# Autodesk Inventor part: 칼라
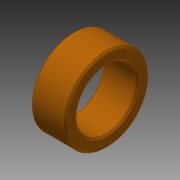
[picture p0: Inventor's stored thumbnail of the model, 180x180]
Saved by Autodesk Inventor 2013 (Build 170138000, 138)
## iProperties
Created: 2015-09
Part Number: 칼라
Material: 강철, 연강
Document SubType Name: Modeling
Designer: mduedu
Density: 7.86 g/cm^3
Description: 외주 가공
Mass: 17.8983 g
Surface Area: 15.6581 cm^2
Volume: 2.27713 cm^3
Author: mduedu
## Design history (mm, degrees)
sketch "스케치1"
  geometry: C1 r 12 at (0, 0); C2 r 8.5 at (0, 0); 1 further point
  constraints: 2 centre point, 2 coincident
  dimensions: "d0" = 24 diameter of C1; "d2" = 17 diameter of C2
extrude "돌출1" new body sketch "스케치1" distance "d3" = 10; taper "d4" = 0 deg
chamfer "모따기1" distance "d5" = 0.5; stored, may be unused: second distance "d6" = 2, angle "d7" = 45 deg
node "솔리드1"
